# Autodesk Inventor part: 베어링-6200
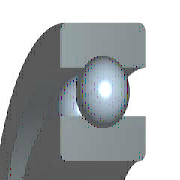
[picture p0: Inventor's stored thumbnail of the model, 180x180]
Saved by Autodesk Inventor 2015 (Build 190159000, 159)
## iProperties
Created: 2012-02
Part Number: 베어링-6200
Material: 강철, 연강
Description: 깊은 그루브 볼 베어링
Document SubType Name: Modeling
Standard: KS B 2023
Designer: mduedu
Standards Organization: KS
Language: ko-KR
Size Designation: 6200 - 10 x 30 x 9
Categories: <MemberInstance><Categories><Category DisplayName="샤프트 부품" InternalName="7f7aeb1f-a693-4053-b835-cee3144e0d98" Mnemonic="SHFT"><Category DisplayName="베어링" Inter
Density: 1 g/cm^3
Appearance: 노란색
IsCustomPart: 1
Author: mduedu
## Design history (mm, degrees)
sketch "스케치" dims "d0" = 5.2 (= -0.26 x WD + 0.26 x BD)
  geometry: L1 (1.9, 10)-(7.1, 10); L2 (4.5, 10)-(4.5, 7.4); L3 (4.5, 10)-(4.5, 12.6); L4 (2.568, 8.26)-(0, 8.26); L5 (0, 5)-(9, 5); L6 (2.568, 11.74)-(0, 11.74); L7 (0, 15)-(9, 15); L8 (9, 5)-(9, 8.26); L9 (6.432, 8.26)-(9, 8.26); L10 (6.432, 11.74)-(9, 11.74); L11 (9, 15)-(9, 11.74); L12 (-1.4, 0)-(8.4, 0) reference; L13 (0, -0.3)-(0, 5.3) reference
  constraints: 22 end point, 4 point on line, 2 collinear, 2 perpendicular, 2 symmetric about line, 1 midpoint, 1 parallel, 14 other
  dimensions: "d9" = 10 diameter of L5 L12 (= WD); "d11" = 30 diameter of L7 L12 (= BD); "d12" = 9 distance between parallel lines of L8 L13 (= KB); "d13" = 16.52 diameter of L9 L12 (= 0.326 x BD + 0.674 x WD)
revolve "본체" stored, may be unused: angle "d6" = 90 deg
revolve "볼" stored, may be unused: angle "d7" = 90 deg
pattern_circular "IDS_ARRAYBALL[SIMPL:T]" dims angle "d3" = 360 deg
body "Solid1"
fillet "모깎기1" dims "d1" = 0.6 (= KRS)
other parameters: "WD" = 10 [user parameter; used in 5 equation terms], "BD" = 30 [user parameter; used in 5 equation terms], "KB" = 9 [user parameter; used in 1 equation term], "KRS" = 0.6 [user parameter; used in 1 equation term], "d4" = 0, "d5" = 0, "d8" = 0, "d14" = 0, "d15" = 0, "BBA" = 0 [user parameter], "BC0" = 2360000 [user parameter], "BC" = 5070000 [user parameter], "BR" = 15 (= 0.5 x BD) [user parameter], "WR" = 5 (= 0.5 x WD) [user parameter]
